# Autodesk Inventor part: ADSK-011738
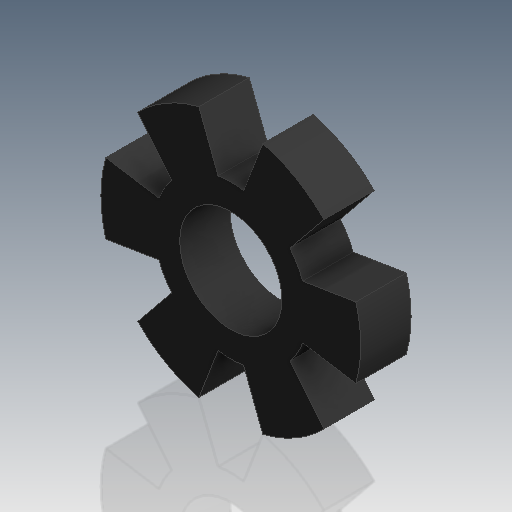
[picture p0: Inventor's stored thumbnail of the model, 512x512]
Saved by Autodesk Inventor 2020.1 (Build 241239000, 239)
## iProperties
Created: 2000-03
Part Number: ADSK-011738
Material: Pearson HRS
Description: COUPLING,SPIDER,L090/L100, STANDARD INSERT
Document SubType Name: Modeling
Designer: cmcgourin
Density: 7.83 g/cm^3
Appearance: Rubber-Black
Mass: 183.387 g
Surface Area: 85.5792 cm^2
Volume: 23.4211 cm^3
Control State: 0
Master: False
Checked Out: False
Shininess: 0.0
Length Units: 11269
Angle Units: 11279
Time Units: 11290
Mass Units: 11283
Length Display Precision: 3
Angle Display Precision: 2
Compacted: True
Cutlength: 23.25
Material Desc: Material Description goes here
Material_Number: Pearson
Dimensions: 62,5x12,5x64,5 mm
Mass: 0,183 kg
VLT_Material: Pearson HRS
Density: 0.0
Volumn: 0.0
Area: 0.0
PropertySet Name: Model Information
Author: cmcgourin
Revision Number: -
Title: COUPLING,SPIDER,L090/L100, STANDARD INSERT
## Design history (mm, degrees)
node "Solide1"
  node "Extrusion1" dims "d0" = 12.5, "d1" = 0
sketch "Sketch1"
  geometry: L1 (-17.855, 6.642)-(-31.046, 8.759) reference; L2 (-23.109, 22.507)-(-14.68, 12.141) reference; L3 (-3.175, 18.784)-(-7.938, 31.266) reference; L4 (7.938, 31.266)-(3.175, 18.784) reference; L5 (31.046, 8.759)-(17.855, 6.642) reference; L6 (14.68, 12.141)-(23.109, 22.507) reference; L7 (17.855, -6.642)-(31.046, -8.759) reference; L8 (23.109, -22.507)-(14.68, -12.141) reference; L9 (3.175, -18.784)-(7.938, -31.266) reference; L10 (-7.938, -31.266)-(-3.175, -18.784) reference; L11 (-14.68, -12.141)-(-23.109, -22.507) reference; L12 (-31.046, -8.759)-(-17.855, -6.642) reference; C1 r 12.7 at (0, 0) reference; A1 r 32.258 centre (0, 0) between (-7.938, 31.266) and (-23.109, 22.507) reference; A2 r 32.258 centre (0, 0) between (-23.109, 22.507) and (-31.046, 8.759) reference; A3 r 32.258 centre (0, 0) between (-31.046, 8.759) and (-31.046, -8.759) reference; A4 r 19.05 centre (0, 0) between (-14.68, 12.141) and (-17.855, 6.642) reference; A5 r 19.05 centre (0, 0) between (3.175, 18.784) and (-3.175, 18.784) reference; A6 r 32.258 centre (0, 0) between (7.938, 31.266) and (-7.938, 31.266) reference; A7 r 32.258 centre (0, 0) between (23.109, 22.507) and (7.938, 31.266) reference; A8 r 32.258 centre (0, 0) between (31.046, 8.759) and (23.109, 22.507) reference; A9 r 19.05 centre (0, 0) between (17.855, 6.642) and (14.68, 12.141) reference; A10 r 32.258 centre (0, 0) between (31.046, -8.759) and (31.046, 8.759) reference; A11 r 19.05 centre (0, 0) between (14.68, -12.141) and (17.855, -6.642) reference; A12 r 32.258 centre (0, 0) between (23.109, -22.507) and (31.046, -8.759) reference; A13 r 32.258 centre (0, 0) between (7.938, -31.266) and (23.109, -22.507) reference; A14 r 19.05 centre (0, 0) between (-3.175, -18.784) and (3.175, -18.784) reference; A15 r 32.258 centre (0, 0) between (-7.938, -31.266) and (7.938, -31.266) reference; A16 r 32.258 centre (0, 0) between (-23.109, -22.507) and (-7.938, -31.266) reference; A17 r 19.05 centre (0, 0) between (-17.855, -6.642) and (-14.68, -12.141) reference; A18 r 32.258 centre (0, 0) between (-31.046, -8.759) and (-23.109, -22.507) reference; 1 further point
node "Corps solides"
node "Corps surfaciques"
